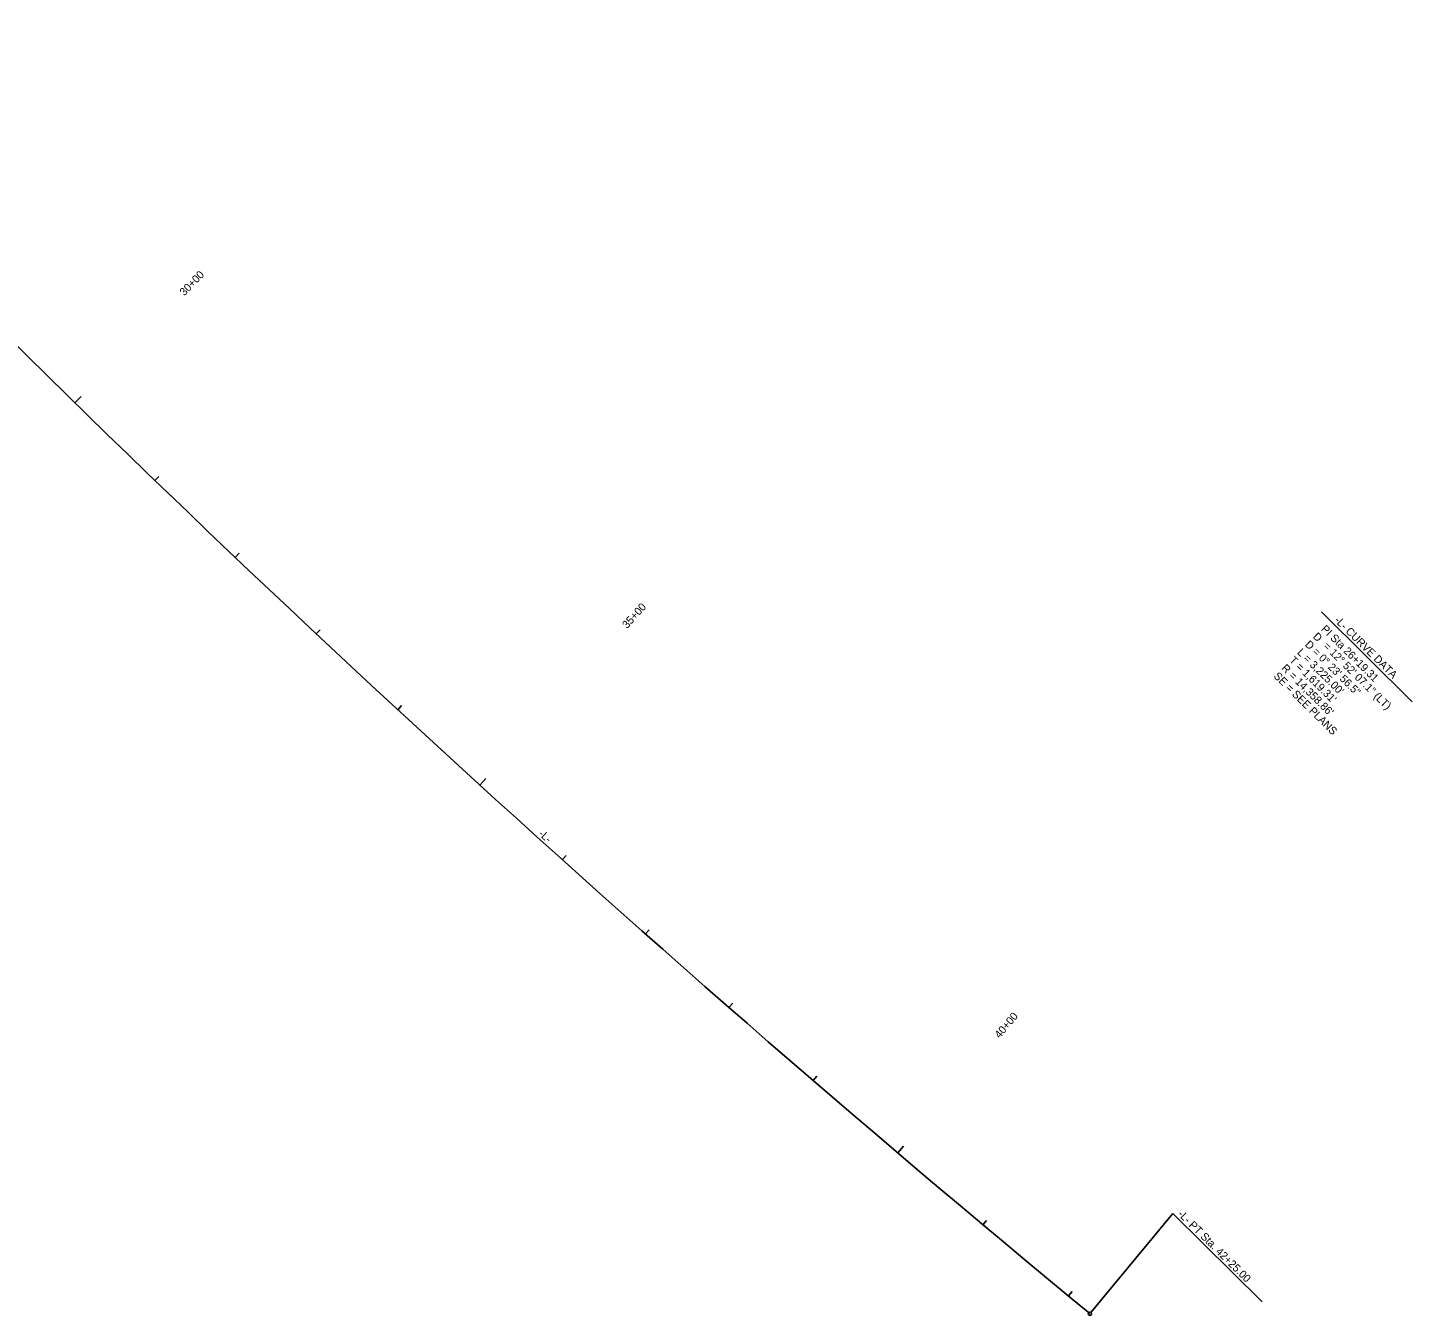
# Model space of a CAD drawing. Extents: x 1602281 to 1604813, y 908112 to 910586.
# Drawn here: x 1603569 to 1604813, y 908112 to 909268 of the extents above; entities that cross this region are included whole.
import ezdxf

# ---------------------------------------------------------------- set-up
doc = ezdxf.new("R2010")
doc.units = 0
for name, color, linetype in [('Exist Environmental Endangered Plant Boundary Cogo Point CELL', 7, 'Continuous'), ('Exist Environmental Wetland Boundary Cogo Comment', 7, 'Continuous'), ('Exist Environmental Wetland Boundary Cogo Elevation', 7, 'Continuous'), ('Exist Hydro Jurisdictional Stream or Body of Water NEU Mitigable Cogo Comment', 7, 'Continuous'), ('Exist Hydro Jurisdictional Stream or Body of Water NEU Mitigable Cogo Elevation', 7, 'Continuous'), ('Exist Hydro Jurisdictional Stream or Body of Water NEU Mitigable Cogo Point CELL', 7, 'Continuous'), ('Exist Hydro Jurisdictional Stream or Body of Water NEU NonMitigable', 7, 'Continuous')]:
    doc.layers.add(name, color=color, linetype=linetype)

msp = doc.modelspace()

# ---------------------------------------------------------------- linework, layer by layer
at = {"layer": 'Exist Environmental Endangered Plant Boundary Cogo Point CELL'}
msp.add_line((1604731.4, 908743.7), (1604812.9, 908663.1), dxfattribs=at)
at = {"layer": 'Exist Environmental Wetland Boundary Cogo Comment'}
for p, q in [((1603683.5, 908861.8), (1603687, 908865.4)), ((1603755.8, 908792.7), (1603759.2, 908796.3)), ((1603828.5, 908724), (1603831.9, 908727.7)), ((1603901.7, 908655.9), (1603905.1, 908659.6)), ((1604049.5, 908521.2), (1604052.9, 908524.9)), ((1604124.2, 908454.6), (1604127.5, 908458.4)), ((1604199.2, 908388.6), (1604202.5, 908392.4)), ((1604274.8, 908323.1), (1604278, 908326.8)), ((1604427.2, 908193.6), (1604430.4, 908197.4)), ((1604504.1, 908129.7), (1604507.3, 908133.5))]:
    msp.add_line(p, q, dxfattribs=at)
msp.add_circle((1604523.4, 908113.7), 1.5, dxfattribs=at)
at = {"layer": 'Exist Environmental Wetland Boundary Cogo Elevation'}
for p, q in [((1603611.7, 908931.4), (1603617.3, 908937.2)), ((1603975.4, 908588.3), (1603980.8, 908594.2)), ((1604350.8, 908258.1), (1604355.9, 908264.2))]:
    msp.add_line(p, q, dxfattribs=at)
at = {"layer": 'Exist Hydro Jurisdictional Stream or Body of Water NEU Mitigable Cogo Comment'}
for p, q in [((1604524.3, 908114.9), (1604597.7, 908203.7)), ((1604597.7, 908203.7), (1604678, 908124.3))]:
    msp.add_line(p, q, dxfattribs=at)
at = {"layer": 'Exist Hydro Jurisdictional Stream or Body of Water NEU Mitigable Cogo Point CELL'}
msp.add_arc((1613646.3, 919202), 14358.9, 217.68536, 230.55399, dxfattribs=at)
at = {"layer": 'Exist Hydro Jurisdictional Stream or Body of Water NEU NonMitigable'}
msp.add_arc((1613646.3, 919202), 14358.9, 217.68536, 230.55399, dxfattribs=at)

# ---------------------------------------------------------------- texts
at = {"layer": 'Exist Environmental Endangered Plant Boundary Cogo Point CELL'}
for s, rotation, p in [('PI Sta 26+19.31', 315.2976, (1604730.6, 908727.7)), ('-L- CURVE DATA', 315.2975, (1604742.5, 908735.6)), ('D', 315.2976, (1604723.1, 908721)), ("L = 3,225.00'", 315.2976, (1604709, 908706.8)), ('D = 0%%d 23\' 56.5"', 315.2976, (1604716, 908713.9)), ('= 12%%d 52\' 07.1" (LT)', 315.2976, (1604732.4, 908712.2)), ("R = 14,358.86'", 315.2976, (1604694.9, 908692.6)), ("T = 1,619.31'", 315.2976, (1604702, 908699.7)), ('SE = SEE PLANS', 315.2976, (1604687.9, 908685.5))]:
    msp.add_text(s, height=7, rotation=rotation, dxfattribs=at).set_placement(p)
at = {"layer": 'Exist Hydro Jurisdictional Stream or Body of Water NEU Mitigable Cogo Comment'}
msp.add_text('-L- PT Sta. 42+25.00', height=7, rotation=315.2976, dxfattribs=at).set_placement((1604601.8, 908202.5))
at = {"layer": 'Exist Hydro Jurisdictional Stream or Body of Water NEU Mitigable Cogo Elevation'}
for s, rotation, p in [('30+00', 45.6659, (1603710, 909027)), ('35+00', 47.661, (1604107.7, 908728.3)), ('40+00', 49.6562, (1604442.3, 908360.4))]:
    msp.add_text(s, height=7, rotation=rotation, dxfattribs=at).set_placement(p)
at = {"layer": 'Exist Hydro Jurisdictional Stream or Body of Water NEU NonMitigable'}
msp.add_text('-L-', height=7, rotation=317.9693, dxfattribs=at).set_placement((1604027.6, 908543.7))

doc.saveas('drawing.dxf')
